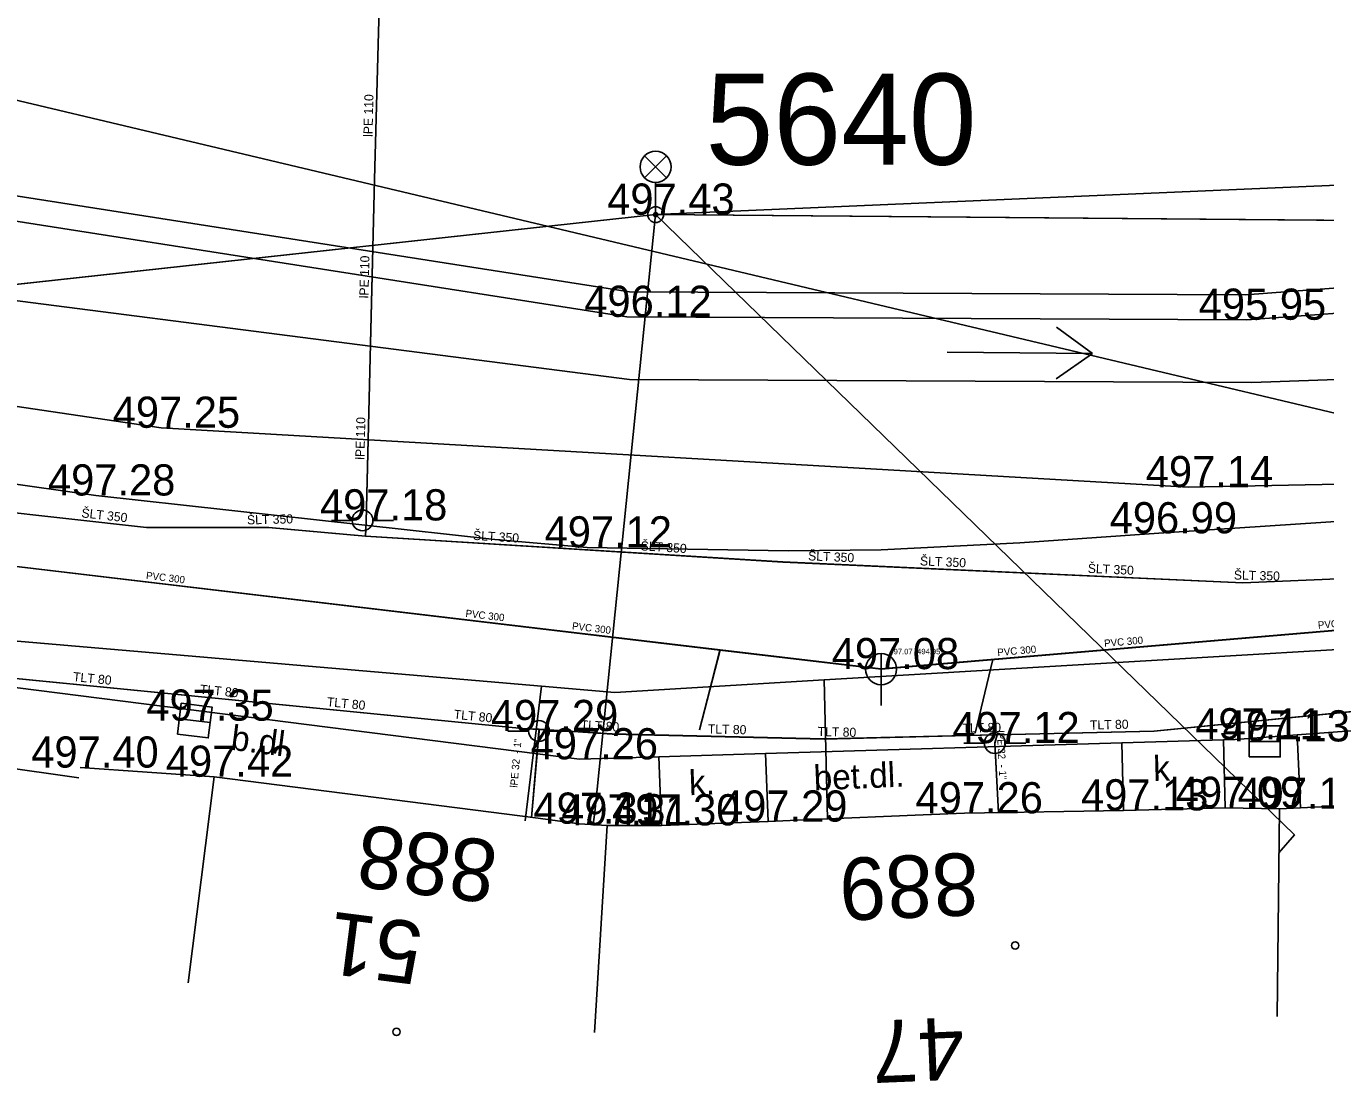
# Model space of a CAD drawing. Extents: x -669642 to -669119, y -1131006 to -1130466.
# Drawn here: x -669544 to -669512.68, y -1130645.94 to -1130620.5 of the extents above; entities that cross this region are included whole.
import ezdxf

# ---------------------------------------------------------------- set-up
doc = ezdxf.new("R2010")
doc.units = 0
for name, color, linetype in [('G_Bod_tecka', 7, 'Continuous'), ('G_Bod_vyska', 7, 'Continuous'), ('G_Budovy-znacky', 7, 'Continuous'), ('G_Budovy_Objekty', 7, 'Continuous'), ('G_Budovy_vstupy', 7, 'Continuous'), ('G_Cesty_Schody', 7, 'Continuous'), ('G_Cisla_orientacni', 7, 'Continuous'), ('G_Cisla_popisna', 7, 'Continuous'), ('G_Objekty_technicke', 7, 'Continuous'), ('G_Plochy_zpevnene', 7, 'Continuous'), ('G_Ploty', 7, 'Continuous'), ('G_Ploty_vstupy', 7, 'Continuous'), ('G_Popisy_Nazvy', 7, 'Continuous'), ('G_Popisy_povrchu', 7, 'Continuous'), ('G_Site-kanalizace', 7, 'Continuous'), ('G_Site-vodovod', 7, 'Continuous'), ('G_Z_ELsilove_nadz_kotovane', 7, 'Continuous'), ('G_Z_ELsilove_podz_kotovane', 7, 'Continuous'), ('G_Z_KANAL_podz_kotovane', 7, 'Continuous'), ('G_Z_PLYNY_podz_geodeticky', 7, 'Continuous'), ('G_Z_SPOJE_nadz_kotovane', 7, 'Continuous'), ('G_Z_VODA_podz_kotovane', 7, 'Continuous'), ('G_Zabradli_Svodidla', 7, 'Continuous'), ('Vrstva 1', 7, 'Continuous'), ('Vrstva 11', 7, 'Continuous'), ('Vrstva 16', 7, 'Continuous'), ('Vrstva 2', 7, 'Continuous'), ('Vrstva 26', 7, 'Continuous'), ('Vrstva 3', 7, 'Continuous'), ('Vrstva 4', 7, 'Continuous'), ('Vrstva 6', 7, 'Continuous'), ('Vrstva 62', 7, 'Continuous'), ('Vrstva 8', 7, 'Continuous')]:
    doc.layers.add(name, color=color, linetype=linetype)

msp = doc.modelspace()

# ---------------------------------------------------------------- linework, layer by layer
at = {"layer": 'G_Bod_tecka'}
for p, q in [((-669528.83, -1130625.04), (-669528.83, -1130625.04)), ((-669529.52, -1130627.5), (-669529.52, -1130627.5)), ((-669514.59, -1130627.57), (-669514.59, -1130627.57)), ((-669540.74, -1130630.17), (-669540.74, -1130630.17)), ((-669516, -1130631.6), (-669516, -1130631.6)), ((-669542.31, -1130631.8), (-669542.31, -1130631.8)), ((-669535.89, -1130632.4), (-669535.89, -1130632.4)), ((-669516.71, -1130632.71), (-669516.71, -1130632.71)), ((-669530.48, -1130633.05), (-669530.48, -1130633.05)), ((-669523.4, -1130635.98), (-669523.4, -1130635.98)), ((-669539.93, -1130637.22), (-669539.93, -1130637.22)), ((-669531.64, -1130637.47), (-669531.64, -1130637.47)), ((-669520.66, -1130637.76), (-669520.66, -1130637.76)), ((-669514.87, -1130637.67), (-669514.87, -1130637.67)), ((-669514.16, -1130637.72), (-669514.16, -1130637.72)), ((-669530.66, -1130638.15), (-669530.66, -1130638.15)), ((-669542.69, -1130638.35), (-669542.69, -1130638.35)), ((-669539.46, -1130638.57), (-669539.46, -1130638.57)), ((-669521.39, -1130639.45), (-669521.39, -1130639.45)), ((-669517.56, -1130639.38), (-669517.56, -1130639.38)), ((-669515.11, -1130639.32), (-669515.11, -1130639.32)), ((-669513.8, -1130639.34), (-669513.8, -1130639.34)), ((-669530.67, -1130639.7), (-669530.67, -1130639.7)), ((-669530, -1130639.74), (-669530, -1130639.74)), ((-669528.69, -1130639.74), (-669528.69, -1130639.74)), ((-669526.12, -1130639.65), (-669526.12, -1130639.65))]:
    msp.add_line(p, q, dxfattribs=at)
at = {"layer": 'G_Budovy-znacky'}
for centre in [(-669520.17, -1130642.631), (-669535.07, -1130644.711)]:
    msp.add_circle(centre, 0.0875, dxfattribs=at)
at = {"layer": 'G_Budovy_Objekty'}
for p, q in [((-669540.09, -1130643.53), (-669539.46, -1130638.57)), ((-669539.46, -1130638.57), (-669531.66, -1130639.57)), ((-669525.06, -1130639.6), (-669522.39, -1130639.49)), ((-669521.39, -1130639.45), (-669517.56, -1130639.38)), ((-669515.11, -1130639.32), (-669513.8, -1130639.34)), ((-669513.86, -1130644.34), (-669513.8, -1130639.34)), ((-669513.8, -1130639.34), (-669513.3, -1130639.32)), ((-669530.67, -1130639.7), (-669530, -1130639.74)), ((-669530.3, -1130644.73), (-669530, -1130639.74)), ((-669530, -1130639.74), (-669528.69, -1130639.74)), ((-669526.12, -1130639.65), (-669525.06, -1130639.6))]:
    msp.add_line(p, q, dxfattribs=at)
at = {"layer": 'G_Budovy_vstupy'}
for p, q in [((-669510.88, -1130639.2), (-669513.3, -1130639.32)), ((-669521.39, -1130639.45), (-669522.39, -1130639.49)), ((-669515.11, -1130639.32), (-669517.56, -1130639.38)), ((-669530.67, -1130639.7), (-669531.66, -1130639.57)), ((-669526.12, -1130639.65), (-669528.69, -1130639.74))]:
    msp.add_line(p, q, dxfattribs=at)
at = {"layer": 'G_Cesty_Schody'}
for points in [[(-669513.38, -1130637.56), (-669513.3, -1130639.32)], [(-669517.6, -1130637.75), (-669517.56, -1130639.38)], [(-669515.15, -1130637.68), (-669515.11, -1130639.32)], [(-669528.75, -1130638.09), (-669528.69, -1130639.74)], [(-669526.18, -1130638.01), (-669526.12, -1130639.65)]]:
    msp.add_lwpolyline(points, dxfattribs=at)
at = {"layer": 'G_Objekty_technicke'}
for p, q in [((-669529.095, -1130623.625), (-669528.565, -1130624.155)), ((-669529.095, -1130624.155), (-669528.565, -1130623.625)), ((-669528.83, -1130625.04), (-669528.83, -1130624.265))]:
    msp.add_line(p, q, dxfattribs=at)
for centre, radius in [((-669528.83, -1130623.89), 0.375), ((-669528.83, -1130625.04), 0.19), ((-669528.83, -1130625.04), 0.05)]:
    msp.add_circle(centre, radius, dxfattribs=at)
at = {"layer": 'G_Plochy_zpevnene'}
for p, q in [((-669529.46, -1130626.9), (-669548.77, -1130623.88)), ((-669548.89, -1130624.47), (-669529.52, -1130627.5)), ((-669561.55, -1130624.88), (-669529.46, -1130629.01)), ((-669492.02, -1130625.28), (-669514.62, -1130626.97)), ((-669491.63, -1130625.86), (-669514.59, -1130627.57)), ((-669514.62, -1130626.97), (-669529.46, -1130626.9)), ((-669514.59, -1130627.57), (-669529.52, -1130627.5)), ((-669514.47, -1130629.08), (-669491.94, -1130628.25)), ((-669529.46, -1130629.01), (-669514.47, -1130629.08)), ((-669550.16, -1130630.69), (-669542.31, -1130631.8)), ((-669550, -1130635.69), (-669530.66, -1130638.15)), ((-669513.38, -1130637.56), (-669514.87, -1130637.67)), ((-669510.96, -1130637.38), (-669513.38, -1130637.56)), ((-669517.6, -1130637.75), (-669526.18, -1130638.01)), ((-669515.15, -1130637.68), (-669517.6, -1130637.75)), ((-669514.87, -1130637.67), (-669515.15, -1130637.68)), ((-669528.75, -1130638.09), (-669530.66, -1130638.15)), ((-669526.18, -1130638.01), (-669528.75, -1130638.09))]:
    msp.add_line(p, q, dxfattribs=at)
for points in [[(-669530.48, -1130633.05), (-669528.06, -1130633.09), (-669525.63, -1130633.13), (-669523.4, -1130633.11), (-669520.06, -1130632.94), (-669516.71, -1130632.71), (-669511.47, -1130632.36), (-669506.22, -1130631.96), (-669499.63, -1130631.35), (-669493.05, -1130630.68), (-669484.15, -1130629.72), (-669475.25, -1130628.76), (-669469.76, -1130628.17), (-669464.26, -1130627.57), (-669451.38, -1130626.21), (-669438.5, -1130624.92)], [(-669530.48, -1130633.05), (-669532.7, -1130632.86), (-669542.31, -1130631.8)]]:
    msp.add_lwpolyline(points, dxfattribs=at)
at = {"layer": 'G_Ploty'}
msp.add_line((-669546.91, -1130638), (-669542.72, -1130638.6), dxfattribs=at)
at = {"layer": 'G_Ploty_vstupy'}
msp.add_line((-669539.46, -1130638.57), (-669542.69, -1130638.35), dxfattribs=at)
at = {"layer": 'G_Popisy_Nazvy'}
for p, q in [((-669519.173, -1130627.751), (-669518.31, -1130628.38)), ((-669521.81, -1130628.346), (-669518.31, -1130628.38)), ((-669518.31, -1130628.38), (-669519.185, -1130628.992))]:
    msp.add_line(p, q, dxfattribs=at)
at = {"layer": 'G_Site-kanalizace'}
for points in [[(-669523.4, -1130635.605), (-669523.4, -1130636.855)], [(-669540.302, -1130637.174), (-669539.558, -1130637.266)], [(-669514.535, -1130637.72), (-669513.785, -1130637.72)]]:
    msp.add_lwpolyline(points, dxfattribs=at)
for points in [[(-669540.348, -1130637.545), (-669539.604, -1130637.637), (-669539.512, -1130636.893), (-669540.256, -1130636.801)], [(-669514.535, -1130638.094), (-669513.785, -1130638.094), (-669513.785, -1130637.344), (-669514.535, -1130637.344)]]:
    msp.add_lwpolyline(points, close=True, dxfattribs=at)
msp.add_circle((-669523.4, -1130635.98), 0.375, dxfattribs=at)
at = {"layer": 'G_Site-vodovod'}
for p, q in [((-669536.14, -1130632.4), (-669536.64, -1130632.4)), ((-669535.64, -1130632.4), (-669535.14, -1130632.4))]:
    msp.add_line(p, q, dxfattribs=at)
for points in [[(-669531.89, -1130637.47), (-669532.39, -1130637.47)], [(-669531.39, -1130637.47), (-669530.89, -1130637.47)], [(-669520.91, -1130637.76), (-669521.41, -1130637.76)], [(-669520.41, -1130637.76), (-669519.91, -1130637.76)]]:
    msp.add_lwpolyline(points, dxfattribs=at)
for centre in [(-669535.89, -1130632.4), (-669531.64, -1130637.47), (-669520.66, -1130637.76)]:
    msp.add_circle(centre, 0.25, dxfattribs=at)
at = {"layer": 'G_Z_ELsilove_nadz_kotovane'}
for points in [[(-669467.84, -1130625.55), (-669498.42, -1130623.73), (-669528.83, -1130625.04), (-669557.25, -1130628.14)], [(-669528.83, -1130625.04), (-669530.296, -1130639.425), (-669530.338, -1130639.716)], [(-669528.83, -1130625.04), (-669513.445, -1130639.972), (-669513.816, -1130640.398)]]:
    msp.add_lwpolyline(points, dxfattribs=at)
at = {"layer": 'G_Z_ELsilove_podz_kotovane'}
msp.add_lwpolyline([(-669397.44, -1130624.27), (-669468.22, -1130625.55), (-669528.83, -1130625.04), (-669557.25, -1130628.14), (-669594.17, -1130629.25), (-669631.6, -1130630.45), (-669640.046, -1130636.793)], dxfattribs=at)
at = {"layer": 'G_Z_KANAL_podz_kotovane'}
for p, q in [((-669523.4, -1130635.98), (-669475.53, -1130631.9)), ((-669527.28, -1130635.52), (-669527.77, -1130637.44)), ((-669520.71, -1130635.75), (-669521.13, -1130637.52))]:
    msp.add_line(p, q, dxfattribs=at)
msp.add_lwpolyline([(-669561.34, -1130631.49), (-669552, -1130632.59), (-669545.65, -1130633.34), (-669527.28, -1130635.52), (-669523.4, -1130635.98)], dxfattribs=at)
at = {"layer": 'G_Z_PLYNY_podz_geodeticky'}
for points in [[(-669393.89, -1130633.8), (-669405.53, -1130635.18), (-669408.92, -1130631.07), (-669421.41, -1130629.96), (-669421.75, -1130629.95), (-669422.07, -1130629.92), (-669442.29, -1130629.71), (-669461.19, -1130631.01), (-669464.06, -1130631.31), (-669468.18, -1130631.75), (-669479.12, -1130632.91), (-669492.48, -1130634.32), (-669492.89, -1130634.36), (-669502.75, -1130634.94), (-669524.77, -1130636.24), (-669529.81, -1130636.54), (-669531.58, -1130636.39), (-669545.71, -1130635.18), (-669546.84, -1130634.96), (-669548.48, -1130634.64)], [(-669531.97, -1130639.63), (-669531.58, -1130636.39)], [(-669524.77, -1130636.24), (-669524.69, -1130639.58)]]:
    msp.add_lwpolyline(points, dxfattribs=at)
at = {"layer": 'G_Z_SPOJE_nadz_kotovane'}
msp.add_lwpolyline([(-669556.92, -1130619.27), (-669509.9, -1130630.43)], dxfattribs=at)
at = {"layer": 'G_Z_VODA_podz_kotovane'}
for points in [[(-669635.26, -1130590.81), (-669630.49, -1130595.57), (-669625.14, -1130600.6), (-669618.08, -1130606.31), (-669611.07, -1130612.13), (-669604.25, -1130617.94), (-669597.57, -1130623.59), (-669596.09, -1130624.73), (-669595.07, -1130625.23), (-669593.75, -1130625.32), (-669588.96, -1130625.85), (-669577.09, -1130627.78), (-669569.16, -1130629), (-669567.55, -1130629.35), (-669552.61, -1130631.29), (-669541.09, -1130632.57), (-669538.15, -1130632.57), (-669535.82, -1130632.78)], [(-669535.82, -1130632.78), (-669535.8, -1130632.43), (-669535.6, -1130624.19), (-669535.33, -1130614.15), (-669535.11, -1130604.43), (-669534.95, -1130600.22), (-669534.74, -1130594.27), (-669534.72, -1130593.93)], [(-669401.33, -1130628.93), (-669447.15, -1130627.86), (-669501.14, -1130633.33), (-669514.69, -1130633.9), (-669525.77, -1130633.4), (-669535.82, -1130632.78)], [(-669426.33, -1130630.65), (-669450.73, -1130631.94), (-669463.85, -1130632.84), (-669465.88, -1130632.99), (-669466.05, -1130633), (-669479.56, -1130633.86), (-669491.9, -1130634.83), (-669492.19, -1130634.85), (-669496.35, -1130635.39), (-669498.21, -1130635.64), (-669499.83, -1130635.79), (-669516.83, -1130637.47), (-669520.6, -1130637.56), (-669520.67, -1130637.56), (-669524.77, -1130637.66), (-669529.88, -1130637.54), (-669531.63, -1130637.43), (-669531.96, -1130637.42), (-669546.93, -1130635.94)], [(-669531.63, -1130637.43), (-669531.64, -1130637.47), (-669531.82, -1130639.55)], [(-669520.6, -1130637.56), (-669520.66, -1130637.76), (-669520.57, -1130639.44)]]:
    msp.add_lwpolyline(points, dxfattribs=at)
at = {"layer": 'G_Zabradli_Svodidla'}
for p, q in [((-669555.85, -1130627.94), (-669540.74, -1130630.17)), ((-669516, -1130631.6), (-669540.74, -1130630.17)), ((-669505, -1130631.39), (-669516, -1130631.6))]:
    msp.add_line(p, q, dxfattribs=at)
at = {"layer": 'Vrstva 1'}
msp.add_line((-669528.83, -1130625.04), (-669528.83, -1130625.04), dxfattribs=at)
at = {"layer": 'Vrstva 11'}
msp.add_line((-669523.402, -1130635.975), (-669475.532, -1130631.901), dxfattribs=at)
msp.add_lwpolyline([(-669561.339, -1130631.485), (-669552.004, -1130632.59), (-669545.649, -1130633.342), (-669527.277, -1130635.516), (-669523.402, -1130635.975)], dxfattribs=at)
at = {"layer": 'Vrstva 16'}
for p, q in [((-669527.277, -1130635.516), (-669527.773, -1130637.444)), ((-669520.712, -1130635.746), (-669521.133, -1130637.523))]:
    msp.add_line(p, q, dxfattribs=at)
at = {"layer": 'Vrstva 26'}
for points in [[(-669635.26, -1130590.81), (-669630.49, -1130595.57), (-669625.14, -1130600.6), (-669618.08, -1130606.31), (-669611.07, -1130612.13), (-669604.25, -1130617.94), (-669597.57, -1130623.59), (-669596.09, -1130624.73), (-669595.07, -1130625.23), (-669593.75, -1130625.32), (-669588.96, -1130625.85), (-669577.09, -1130627.78), (-669569.16, -1130629), (-669567.55, -1130629.35), (-669552.61, -1130631.29), (-669541.09, -1130632.57), (-669538.152, -1130632.567), (-669535.819, -1130632.776)], [(-669535.819, -1130632.776), (-669535.799, -1130632.427), (-669535.6, -1130624.19), (-669535.33, -1130614.15), (-669535.11, -1130604.43), (-669534.95, -1130600.22), (-669534.74, -1130594.27), (-669534.72, -1130593.93)], [(-669401.333, -1130628.932), (-669447.154, -1130627.856), (-669501.14, -1130633.331), (-669514.685, -1130633.901), (-669525.766, -1130633.403), (-669535.819, -1130632.776)], [(-669426.331, -1130630.645), (-669450.727, -1130631.943), (-669463.848, -1130632.843), (-669465.877, -1130632.987), (-669466.051, -1130632.999), (-669479.557, -1130633.858), (-669491.905, -1130634.829), (-669492.192, -1130634.852), (-669496.35, -1130635.393), (-669498.213, -1130635.635), (-669499.826, -1130635.794), (-669516.826, -1130637.47), (-669520.6, -1130637.561), (-669520.668, -1130637.563), (-669524.77, -1130637.662), (-669529.878, -1130637.544), (-669531.632, -1130637.428), (-669531.955, -1130637.416), (-669546.934, -1130635.937)], [(-669531.632, -1130637.428), (-669531.636, -1130637.473), (-669531.82, -1130639.549)], [(-669520.6, -1130637.561), (-669520.658, -1130637.756), (-669520.569, -1130639.436)]]:
    msp.add_lwpolyline(points, dxfattribs=at)
at = {"layer": 'Vrstva 6'}
for p, q in [((-669535.799, -1130632.427), (-669535.799, -1130632.427)), ((-669531.636, -1130637.473), (-669531.636, -1130637.473)), ((-669520.658, -1130637.756), (-669520.658, -1130637.756))]:
    msp.add_line(p, q, dxfattribs=at)
at = {"layer": 'Vrstva 62'}
for p, q in [((-669528.83, -1130625.04), (-669557.25, -1130628.14)), ((-669468.22, -1130625.55), (-669528.83, -1130625.04))]:
    msp.add_line(p, q, dxfattribs=at)
at = {"layer": 'Vrstva 8'}
msp.add_line((-669523.402, -1130635.975), (-669523.402, -1130635.975), dxfattribs=at)

# ---------------------------------------------------------------- texts
at = {"layer": 'G_Bod_vyska'}
for s, p in [('497.43', (-669529.996, -1130625.04)), ('496.12', (-669530.548, -1130627.5)), ('495.95', (-669515.748, -1130627.57)), ('497.25', (-669541.906, -1130630.17)), ('497.28', (-669543.466, -1130631.8)), ('497.14', (-669517.024, -1130631.6)), ('497.18', (-669536.914, -1130632.4)), ('496.99', (-669517.894, -1130632.71)), ('497.12', (-669531.504, -1130633.05)), ('497.08', (-669524.588, -1130635.98)), ('497.35', (-669541.096, -1130637.22)), ('497.29', (-669532.798, -1130637.47)), ('497.12', (-669521.684, -1130637.76)), ('497.11', (-669515.833, -1130637.67)), ('497.13', (-669515.174, -1130637.72)), ('497.40', (-669543.868, -1130638.35)), ('497.26', (-669531.84, -1130638.15)), ('497.42', (-669540.626, -1130638.57)), ('497.09', (-669516.3, -1130639.32)), ('497.18', (-669514.814, -1130639.34)), ('497.29', (-669527.278, -1130639.65)), ('497.26', (-669522.57, -1130639.45)), ('497.13', (-669518.584, -1130639.38)), ('497.31', (-669531.774, -1130639.7)), ('497.31', (-669531.104, -1130639.74)), ('497.30', (-669529.878, -1130639.74))]:
    msp.add_text(s, height=0.75, dxfattribs=at).set_placement(p)
at = {"layer": 'G_Cisla_orientacni'}
for s, rotation, p in [('51', 172.7258, (-669534.386, -1130642.097)), ('47', 182.4141, (-669521.425, -1130644.353))]:
    msp.add_text(s, height=1.5, rotation=rotation, dxfattribs=at).set_placement(p)
at = {"layer": 'G_Cisla_popisna'}
for s, rotation, p in [('888', 172.7258, (-669532.587, -1130640.136)), ('889', 182.4141, (-669521.086, -1130640.395))]:
    msp.add_text(s, height=1.5, rotation=rotation, dxfattribs=at).set_placement(p)
at = {"layer": 'G_Popisy_povrchu'}
for s, rotation, p in [('b.dl.', 352.7258, (-669539.085, -1130637.917)), ('bet.dl.', 2.4141, (-669525.011, -1130638.899)), ('k.', 1.4292, (-669516.839, -1130638.671)), ('k.', 2.0939, (-669528.018, -1130639.016))]:
    msp.add_text(s, height=0.6, rotation=rotation, dxfattribs=at).set_placement(p)
at = {"layer": 'Vrstva 2'}
msp.add_text('497.07 (494.95)', height=0.13163, dxfattribs=at).set_placement((-669523.197, -1130635.622))
at = {"layer": 'Vrstva 3'}
for rotation, p in [(353.2673, (-669541.111, -1130633.808)), (353.2335, (-669533.416, -1130634.719)), (4.8681, (-669512.871, -1130635.008)), (353.2335, (-669530.85, -1130635.022)), (4.8681, (-669520.593, -1130635.665)), (4.8371, (-669518.02, -1130635.446))]:
    msp.add_text('PVC 300', height=0.1755, rotation=rotation, dxfattribs=at).set_placement(p)
at = {"layer": 'Vrstva 4'}
msp.add_text('5640', height=2.1939, dxfattribs=at).set_placement((-669527.627, -1130623.838))
for s, height, rotation, p in [('lPE 110', 0.2194, 88.6233, (-669535.65, -1130623.171)), ('lPE 110', 0.2194, 88.623, (-669535.747, -1130627.056)), ('lPE 110', 0.2194, 88.623, (-669535.844, -1130630.941)), ('ŠLT 350', 0.2194, 353.6788, (-669542.668, -1130632.324)), ('ŠLT 350', 0.2194, 1.3553, (-669538.67, -1130632.497)), ('ŠLT 350', 0.2194, 356.4719, (-669533.233, -1130632.867)), ('ŠLT 350', 0.2194, 356.4576, (-669529.196, -1130633.119)), ('ŠLT 350', 0.2194, 357.4313, (-669525.161, -1130633.36)), ('ŠLT 350', 0.2194, 357.4313, (-669522.467, -1130633.481)), ('ŠLT 350', 0.2194, 357.4313, (-669518.426, -1130633.662)), ('ŠLT 350', 0.2194, 358.464, (-669514.906, -1130633.821)), ('TLT 80', 0.2194, 354.3497, (-669542.871, -1130636.267)), ('TLT 80', 0.2194, 354.3497, (-669539.814, -1130636.569)), ('TLT 80', 0.2194, 354.3698, (-669536.757, -1130636.871)), ('TLT 80', 0.2194, 354.353, (-669533.7, -1130637.173)), ('TLT 80', 0.2194, 356.4783, (-669530.641, -1130637.426)), ('TLT 80', 0.2194, 358.6537, (-669527.575, -1130637.527)), ('TLT 80', 0.2194, 1.3968, (-669521.437, -1130637.511)), ('TLT 80', 0.2194, 1.3808, (-669518.366, -1130637.436)), ('TLT 80', 0.2194, 358.4472, (-669524.93, -1130637.587)), ('lPE 32  - 1"', 0.17551, 273.023, (-669520.612, -1130637.461)), ('lPE 32  - 1"', 0.17551, 85.0303, (-669532.161, -1130638.838))]:
    msp.add_text(s, height=height, rotation=rotation, dxfattribs=at).set_placement(p)

doc.saveas('drawing.dxf')
